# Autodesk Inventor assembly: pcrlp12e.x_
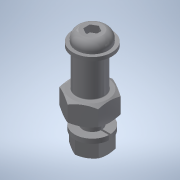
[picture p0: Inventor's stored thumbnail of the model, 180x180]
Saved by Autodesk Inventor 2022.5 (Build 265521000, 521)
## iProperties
Part Number: pcrlp12e.x_
Material: 一般
Document SubType Name: Assembly
Designer: ImaoCorp
Sending System: SOLIDWORKS 2017-2017317
MC: AMD64
MC_MODEL: Intel64 Family 6 Model 60 Stepping 3, GenuineIntel
OS: Windows_NT
FRU: Parasolid Version 29.0, build 201,  4-17-2017
FORMAT: text
GUISE: transmit
KEY: pcrlp12e
FILE: pcrlp12e.x_t
DATE: Wed Sep 04 15:35:10 2019
Author: ImaoCorp
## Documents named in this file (4)
- X:\14_SW2022-Inv2022\00_全2023-1023新製品(TCC)まで\p\pcrlp12e\PCRLP12E.iam
- X:\14_SW2022-Inv2022\00_全2023-1023新製品(TCC)まで\p\pcrlp12e\pcrlp12e_01.ipt
- X:\14_SW2022-Inv2022\00_全2023-1023新製品(TCC)まで\p\pcrlp12e\pcrlp12e_02.ipt
- X:\14_SW2022-Inv2022\00_全2023-1023新製品(TCC)まで\p\pcrlp12e\pcrlp12e_03.ipt
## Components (3 placed, 3 different names)
1. pcrlp12e_01
2. pcrlp12e_02
3. pcrlp12e_03
